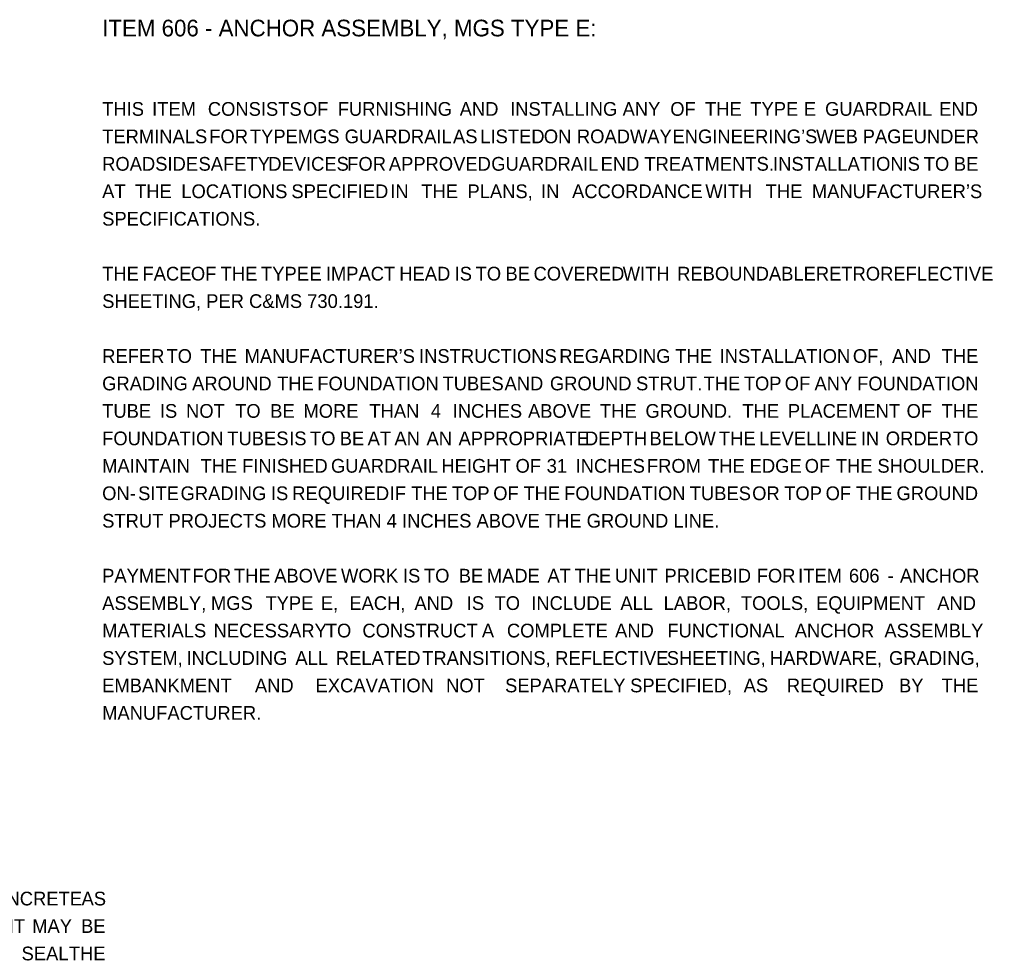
# Model space of a CAD drawing. Extents: x 0 to 64.5, y 0 to 22.
# Drawn here: x 54.55 to 64.48, y 8.18 to 17.78 of the extents above; entities that cross this region are included whole.
import ezdxf

# ---------------------------------------------------------------- set-up
doc = ezdxf.new("R2010")
doc.units = 0
doc.layers.add('SH_Text', color=7, linetype='Continuous')

msp = doc.modelspace()

# ---------------------------------------------------------------- texts
at = {"layer": 'SH_Text'}
for s, height, p in [('ITEM 606 - ANCHOR ASSEMBLY, MGS TYPE E:', 0.17, (55.3971, 17.61)), ('THIS ', 0.14, (55.3971, 16.8)), ('ITEM ', 0.14, (55.9064, 16.8)), ('CONSISTS ', 0.14, (56.4748, 16.8)), ('OF ', 0.14, (57.4446, 16.8)), ('FURNISHING ', 0.14, (57.7993, 16.8)), ('AND ', 0.14, (59.043, 16.8)), ('INSTALLING ', 0.14, (59.5575, 16.8)), ('ANY ', 0.14, (60.704, 16.8)), ('OF ', 0.14, (61.1904, 16.8)), ('THE ', 0.14, (61.5451, 16.8)), ('TYPE ', 0.14, (62.0066, 16.8)), ('E ', 0.14, (62.5523, 16.8)), ('GUARDRAIL ', 0.14, (62.769, 16.8)), ('END ', 0.14, (63.9325, 16.8)), ('TERMINALS ', 0.14, (55.3971, 16.52)), ('FOR ', 0.14, (56.4894, 16.52)), ('TYPE ', 0.14, (56.9036, 16.52)), ('MGS ', 0.14, (57.391, 16.52)), ('GUARDRAIL ', 0.14, (57.8694, 16.52)), ('AS ', 0.14, (58.9747, 16.52)), ('LISTED ', 0.14, (59.2528, 16.52)), ('ON ', 0.14, (59.9011, 16.52)), ('ROADWAY ', 0.14, (60.2384, 16.52)), ('ENGINEERING’S ', 0.14, (61.2129, 16.52)), ('WEB ', 0.14, (62.6775, 16.52)), ('PAGE ', 0.14, (63.1524, 16.52)), ('UNDER ', 0.14, (63.6724, 16.52)), ('ROADSIDE ', 0.14, (55.3971, 16.24)), ('SAFETY ', 0.14, (56.3796, 16.24)), ('DEVICES ', 0.14, (57.0907, 16.24)), ('FOR ', 0.14, (57.8962, 16.24)), ('APPROVED ', 0.14, (58.3205, 16.24)), ('GUARDRAIL ', 0.14, (59.3647, 16.24)), ('END ', 0.14, (60.4801, 16.24)), ('TREATMENTS. ', 0.14, (60.9265, 16.24)), ('INSTALLATION ', 0.14, (62.2385, 16.24)), ('IS ', 0.14, (63.5589, 16.24)), ('TO ', 0.14, (63.7751, 16.24)), ('BE ', 0.14, (64.0821, 16.24)), ('AT ', 0.14, (55.3971, 15.96)), ('THE ', 0.14, (55.7328, 15.96)), ('LOCATIONS ', 0.14, (56.2041, 15.96)), ('SPECIFIED ', 0.14, (57.3268, 15.96)), ('IN ', 0.14, (58.3347, 15.96)), ('THE ', 0.14, (58.6512, 15.96)), ('PLANS, ', 0.14, (59.1224, 15.96)), ('IN ', 0.14, (59.8725, 15.96)), ('ACCORDANCE ', 0.14, (60.189, 15.96)), ('WITH ', 0.14, (61.5479, 15.96)), ('THE ', 0.14, (62.1634, 15.96)), ('MANUFACTURER’S ', 0.14, (62.6347, 15.96)), ('SPECIFICATIONS.', 0.14, (55.3971, 15.68)), ('THE ', 0.14, (55.3971, 15.12)), ('FACE ', 0.14, (55.8081, 15.12)), ('OF ', 0.14, (56.3018, 15.12)), ('THE ', 0.14, (56.6059, 15.12)), ('TYPE ', 0.14, (57.0169, 15.12)), ('E ', 0.14, (57.512, 15.12)), ('IMPACT ', 0.14, (57.6781, 15.12)), ('HEAD ', 0.14, (58.4271, 15.12)), ('IS ', 0.14, (58.9915, 15.12)), ('TO ', 0.14, (59.2053, 15.12)), ('BE ', 0.14, (59.51, 15.12)), ('COVERED ', 0.14, (59.7961, 15.12)), ('WITH ', 0.14, (60.7052, 15.12)), ('REBOUNDABLE ', 0.14, (61.2605, 15.12)), ('RETROREFLECTIVE ', 0.14, (62.6748, 15.12)), ('SHEETING, PER C&MS 730.191.', 0.14, (55.3971, 14.84)), ('REFER ', 0.14, (55.3971, 14.28)), ('TO ', 0.14, (56.0525, 14.28)), ('THE ', 0.14, (56.3979, 14.28)), ('MANUFACTURER’S ', 0.14, (56.8497, 14.28)), ('INSTRUCTIONS ', 0.14, (58.6287, 14.28)), ('REGARDING ', 0.14, (60.0588, 14.28)), ('THE ', 0.14, (61.242, 14.28)), ('INSTALLATION ', 0.14, (61.6937, 14.28)), ('OF, ', 0.14, (63.0525, 14.28)), ('AND ', 0.14, (63.4525, 14.28)), ('THE ', 0.14, (63.9573, 14.28)), ('GRADING ', 0.14, (55.3971, 14)), ('AROUND ', 0.14, (56.3141, 14)), ('THE ', 0.14, (57.181, 14)), ('FOUNDATION ', 0.14, (57.5912, 14)), ('TUBES ', 0.14, (58.8678, 14)), ('AND ', 0.14, (59.4999, 14)), ('GROUND ', 0.14, (59.9631, 14)), ('STRUT. ', 0.14, (60.8415, 14)), ('THE ', 0.14, (61.5297, 14)), ('TOP ', 0.14, (61.9399, 14)), ('OF ', 0.14, (62.3577, 14)), ('ANY ', 0.14, (62.661, 14)), ('FOUNDATION ', 0.14, (63.0961, 14)), ('TUBE ', 0.14, (55.3971, 13.72)), ('IS ', 0.14, (55.9856, 13.72)), ('NOT ', 0.14, (56.2527, 13.72)), ('TO ', 0.14, (56.7527, 13.72)), ('BE ', 0.14, (57.1106, 13.72)), ('MORE ', 0.14, (57.45, 13.72)), ('THAN ', 0.14, (58.1221, 13.72)), ('4 ', 0.14, (58.7485, 13.72)), ('INCHES ', 0.14, (58.972, 13.72)), ('ABOVE ', 0.14, (59.7395, 13.72)), ('THE ', 0.14, (60.4732, 13.72)), ('GROUND. ', 0.14, (60.9375, 13.72)), ('THE ', 0.14, (61.9257, 13.72)), ('PLACEMENT ', 0.14, (62.39, 13.72)), ('OF ', 0.14, (63.5999, 13.72)), ('THE ', 0.14, (63.9573, 13.72)), ('FOUNDATION ', 0.14, (55.3971, 13.44)), ('TUBES ', 0.14, (56.6729, 13.44)), ('IS ', 0.14, (57.3042, 13.44)), ('TO ', 0.14, (57.5164, 13.44)), ('BE ', 0.14, (57.8195, 13.44)), ('AT ', 0.14, (58.104, 13.44)), ('AN ', 0.14, (58.3779, 13.44)), ('AN ', 0.14, (58.7046, 13.44)), ('APPROPRIATE ', 0.14, (59.0313, 13.44)), ('DEPTH ', 0.14, (60.3199, 13.44)), ('BELOW ', 0.14, (60.9782, 13.44)), ('THE ', 0.14, (61.6865, 13.44)), ('LEVEL ', 0.14, (62.0959, 13.44)), ('LINE ', 0.14, (62.6786, 13.44)), ('IN ', 0.14, (63.1336, 13.44)), ('ORDER ', 0.14, (63.3883, 13.44)), ('TO ', 0.14, (64.0723, 13.44)), ('MAINTAIN ', 0.14, (55.3971, 13.16)), ('THE ', 0.14, (56.3995, 13.16)), ('FINISHED ', 0.14, (56.8235, 13.16)), ('GUARDRAIL ', 0.14, (57.7303, 13.16)), ('HEIGHT ', 0.14, (58.8564, 13.16)), ('OF ', 0.14, (59.6126, 13.16)), ('31 ', 0.14, (59.9298, 13.16)), ('INCHES ', 0.14, (60.2248, 13.16)), ('FROM ', 0.14, (60.9522, 13.16)), ('THE ', 0.14, (61.5758, 13.16)), ('EDGE ', 0.14, (61.9999, 13.16)), ('OF ', 0.14, (62.5616, 13.16)), ('THE ', 0.14, (62.8788, 13.16)), ('SHOULDER. ', 0.14, (63.3029, 13.16)), ('ON-', 0.14, (55.3971, 12.88)), ('SITE ', 0.14, (55.7637, 12.88)), ('GRADING ', 0.14, (56.1965, 12.88)), ('IS ', 0.14, (57.1181, 12.88)), ('REQUIRED ', 0.14, (57.3357, 12.88)), ('IF ', 0.14, (58.3285, 12.88)), ('THE ', 0.14, (58.5478, 12.88)), ('TOP ', 0.14, (58.9626, 12.88)), ('OF ', 0.14, (59.385, 12.88)), ('THE ', 0.14, (59.693, 12.88)), ('FOUNDATION ', 0.14, (60.1078, 12.88)), ('TUBES ', 0.14, (61.389, 12.88)), ('OR ', 0.14, (62.0257, 12.88)), ('TOP ', 0.14, (62.3521, 12.88)), ('OF ', 0.14, (62.7745, 12.88)), ('THE ', 0.14, (63.0825, 12.88)), ('GROUND ', 0.14, (63.4973, 12.88)), ('STRUT PROJECTS MORE THAN 4 INCHES ABOVE THE GROUND LINE.', 0.14, (55.3971, 12.6)), ('PAYMENT ', 0.14, (55.3971, 12.04)), ('FOR ', 0.14, (56.3181, 12.04)), ('THE ', 0.14, (56.7403, 12.04)), ('ABOVE ', 0.14, (57.1516, 12.04)), ('WORK ', 0.14, (57.8325, 12.04)), ('IS ', 0.14, (58.4642, 12.04)), ('TO  ', 0.14, (58.6784, 12.04)), ('BE ', 0.14, (59.0332, 12.04)), ('MADE ', 0.14, (59.3196, 12.04)), ('AT ', 0.14, (59.938, 12.04)), ('THE ', 0.14, (60.2138, 12.04)), ('UNIT ', 0.14, (60.6251, 12.04)), ('PRICE ', 0.14, (61.1308, 12.04)), ('BID ', 0.14, (61.7019, 12.04)), ('FOR ', 0.14, (62.0719, 12.04)), ('ITEM ', 0.14, (62.4941, 12.04)), ('606 ', 0.14, (63.0123, 12.04)), ('ANCHOR ', 0.14, (63.5327, 12.04)), ('- ', 0.14, (63.4063, 12.04)), ('ASSEMBLY, ', 0.14, (55.3971, 11.76)), ('MGS ', 0.14, (56.5062, 11.76)), ('TYPE ', 0.14, (57.062, 11.76)), ('E, ', 0.14, (57.6267, 11.76)), ('EACH, ', 0.14, (57.9176, 11.76)), ('AND ', 0.14, (58.5812, 11.76)), ('IS ', 0.14, (59.1149, 11.76)), ('TO ', 0.14, (59.3983, 11.76)), ('INCLUDE ', 0.14, (59.7726, 11.76)), ('ALL ', 0.14, (60.6818, 11.76)), ('LABOR, ', 0.14, (61.1229, 11.76)), ('TOOLS, ', 0.14, (61.9105, 11.76)), ('EQUIPMENT ', 0.14, (62.6767, 11.76)), ('AND ', 0.14, (63.9126, 11.76)), ('MATERIALS ', 0.14, (55.3971, 11.48)), ('NECESSARY ', 0.14, (56.5334, 11.48)), ('TO ', 0.14, (57.6771, 11.48)), ('CONSTRUCT ', 0.14, (58.0508, 11.48)), ('A ', 0.14, (59.2692, 11.48)), ('COMPLETE ', 0.14, (59.5244, 11.48)), ('AND ', 0.14, (60.6276, 11.48)), ('FUNCTIONAL ', 0.14, (61.1606, 11.48)), ('ANCHOR ', 0.14, (62.4597, 11.48)), ('ASSEMBLY ', 0.14, (63.3739, 11.48)), ('SYSTEM, ', 0.14, (55.3971, 11.2)), ('INCLUDING ', 0.14, (56.2569, 11.2)), ('ALL ', 0.14, (57.3671, 11.2)), ('RELATED ', 0.14, (57.7798, 11.2)), ('TRANSITIONS, ', 0.14, (58.66, 11.2)), ('REFLECTIVE ', 0.14, (60.0168, 11.2)), ('SHEETING, ', 0.14, (61.1545, 11.2)), ('HARDWARE, ', 0.14, (62.2063, 11.2)), ('GRADING, ', 0.14, (63.4212, 11.2)), ('EMBANKMENT ', 0.14, (55.3971, 10.92)), ('AND ', 0.14, (56.9549, 10.92)), ('EXCAVATION ', 0.14, (57.5736, 10.92)), ('NOT ', 0.14, (58.9043, 10.92)), ('SEPARATELY ', 0.14, (59.5059, 10.92)), ('SPECIFIED, ', 0.14, (60.781, 10.92)), ('AS ', 0.14, (61.9385, 10.92)), ('REQUIRED ', 0.14, (62.3791, 10.92)), ('BY ', 0.14, (63.5229, 10.92)), ('THE ', 0.14, (63.9573, 10.92)), ('MANUFACTURER.', 0.14, (55.3971, 10.64)), ('CONCRETE ', 0.14, (54.141, 8.7467)), ('AS ', 0.14, (55.187, 8.7467)), ('JOINT ', 0.14, (54.0707, 8.4667)), ('MAY ', 0.14, (54.6839, 8.4667)), ('BE ', 0.14, (55.182, 8.4667)), ('SEAL ', 0.14, (54.5753, 8.1867)), ('THE ', 0.14, (55.0571, 8.1867))]:
    msp.add_text(s, height=height, dxfattribs=at).set_placement(p)

doc.saveas('drawing.dxf')
